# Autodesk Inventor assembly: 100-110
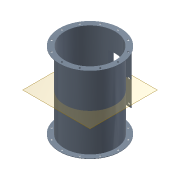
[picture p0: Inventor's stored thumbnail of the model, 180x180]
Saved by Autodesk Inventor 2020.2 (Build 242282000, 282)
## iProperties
Created: 2011-01
Part Number: 100-110
Document SubType Name: Konstrukcja spawana
Designer: F.Stasiak
Weld Material: Spawane aluminium-6061
Company: Fabian Stasiak CAD Consulting
Manager: www.cadconsulting.pl
Author: F.Stasiak
Subject: Zbiór ćwiczeń. Autodesk Inventor 2020. Kurs podstawowy
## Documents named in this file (3)
- C:\2020_Kurs_podstawowy\R6 Zespoły\Kolizja\100-110.iam
- C:\2020_Kurs_podstawowy\R6 Zespoły\Kolizja\100-111.ipt
- C:\2020_Kurs_podstawowy\R6 Zespoły\Kolizja\100-112.ipt
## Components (2 placed, 2 different names)
1. 100-111:1 — Równoległy:1, Styczny:1, Zestawiający:1
2. 100-112:1 — Równoległy:1, Styczny:1, Zestawiający:1
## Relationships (3: Flush 1, Tangent 1, Mate 1)
- Równoległy:1 [Flush]: 100-111:1 ↔ 100-112:1
- Styczny:1 [Tangent]: 100-111:1 ↔ 100-112:1
- Zestawiający:1 [Mate]: 100-111:1 ↔ 100-112:1
